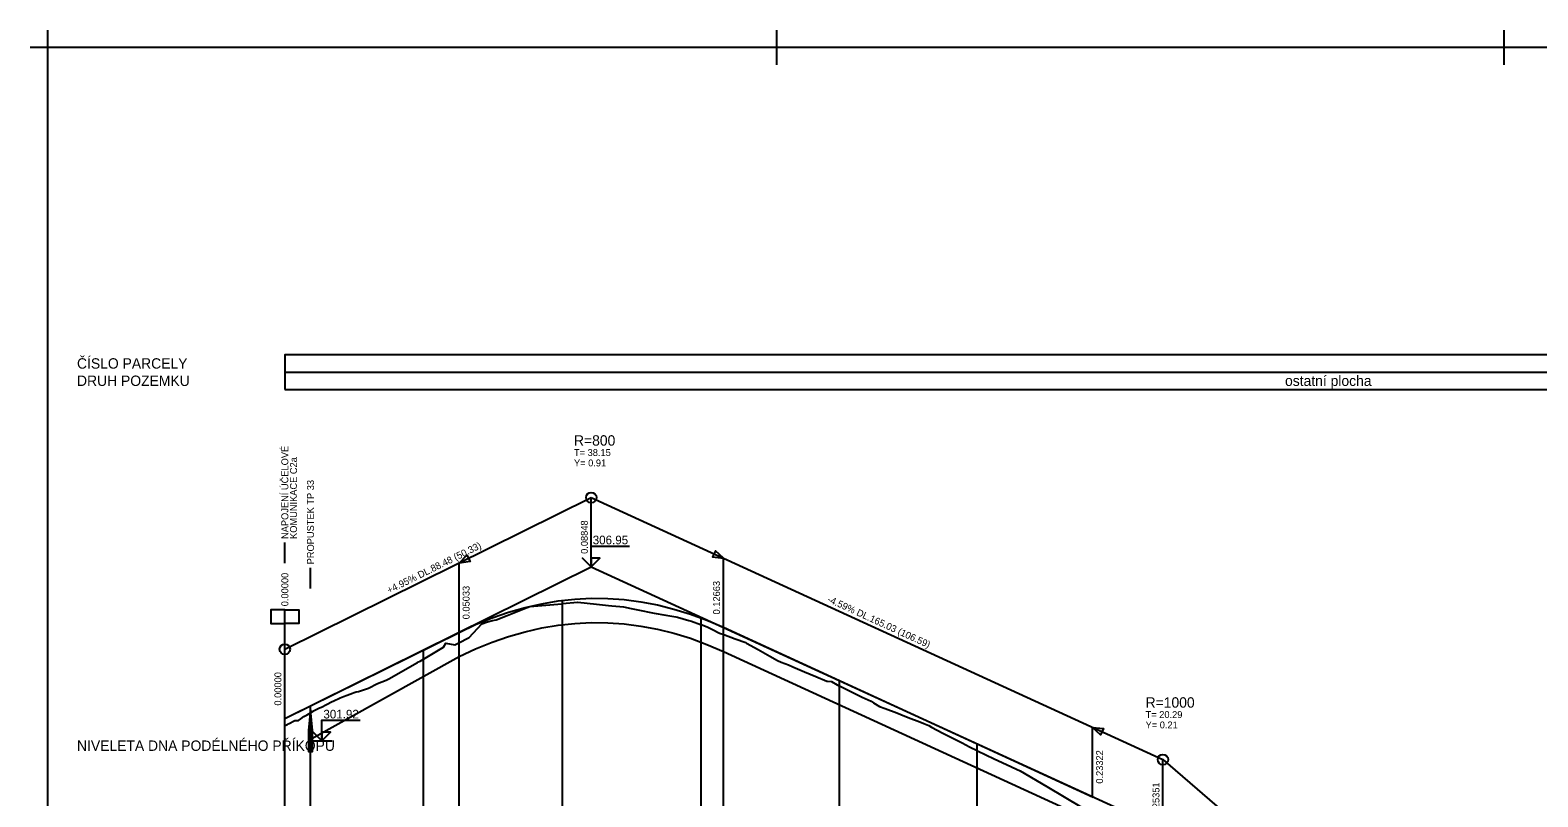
# Model space of a CAD drawing. Extents: x -4 to 847, y -64 to 540.
# Drawn here: x -3.5 to 431.8, y 318.1 to 539.5 of the extents above; entities that cross this region are included whole.
import ezdxf

# ---------------------------------------------------------------- set-up
doc = ezdxf.new("R2010")
doc.units = 0
for name, color, linetype in [('KOTA', 7, 'Continuous'), ('KRIZENI', 7, 'Continuous'), ('NOVY_STAV', 7, 'Continuous'), ('NS_OBLOUK', 7, 'Continuous'), ('POPISY_NAD_TERENEM', 7, 'Continuous'), ('PRIKOPY', 7, 'Continuous'), ('REZY_PO', 7, 'Continuous'), ('SESTAVY_REZU_PO', 7, 'Continuous'), ('SVK_STAT', 7, 'Continuous'), ('TABULKY', 7, 'Continuous'), ('ZNACKY', 7, 'Continuous')]:
    doc.layers.add(name, color=color, linetype=linetype)

msp = doc.modelspace()

# ---------------------------------------------------------------- linework, layer by layer
for p, q in [((1.47, 539.52), (1.47, 529.52)), ((1.47, 539.52), (1.47, 529.52)), ((1.47, 539.52), (1.47, 529.52)), ((1.47, 539.52), (1.47, 529.52)), ((1.47, 539.52), (1.47, 529.52)), ((1.47, 539.52), (1.47, 529.52)), ((1.47, 539.52), (1.47, 529.52)), ((1.47, 539.52), (1.47, 529.52)), ((1.47, 539.52), (1.47, 529.52)), ((1.47, 539.52), (1.47, 529.52)), ((1.47, 539.52), (1.47, 529.52)), ((1.47, 539.52), (1.47, 529.52)), ((1.47, 539.52), (1.47, 529.52)), ((1.47, 539.52), (1.47, 529.52)), ((1.47, 539.52), (1.47, 529.52)), ((1.47, 539.52), (1.47, 529.52)), ((1.47, 539.52), (1.47, 529.52)), ((1.47, 539.52), (1.47, 529.52)), ((1.47, 539.52), (1.47, 529.52)), ((1.47, 539.52), (1.47, 529.52)), ((1.47, 539.52), (1.47, 529.52)), ((1.47, 539.52), (1.47, 529.52)), ((1.47, 539.52), (1.47, 529.52)), ((1.47, 539.52), (1.47, 529.52)), ((1.47, 539.52), (1.47, 529.52)), ((1.47, 539.52), (1.47, 529.52)), ((1.47, 539.52), (1.47, 529.52)), ((1.47, 539.52), (1.47, 529.52)), ((1.47, 539.52), (1.47, 529.52)), ((1.47, 539.52), (1.47, 529.52)), ((1.47, 539.52), (1.47, 529.52)), ((1.47, 539.52), (1.47, 529.52)), ((1.47, 539.52), (1.47, 529.52)), ((1.47, 539.52), (1.47, 529.52)), ((1.47, 539.52), (1.47, 529.52)), ((1.47, 539.52), (1.47, 529.52)), ((1.47, 539.52), (1.47, 529.52)), ((1.47, 539.52), (1.47, 529.52)), ((1.47, 539.52), (1.47, 529.52)), ((1.47, 539.52), (1.47, 529.52)), ((1.47, 539.52), (1.47, 529.52)), ((1.47, 539.52), (1.47, 529.52)), ((1.47, 539.52), (1.47, 529.52)), ((1.47, 539.52), (1.47, 529.52)), ((1.47, 539.52), (1.47, 529.52)), ((1.47, 539.52), (1.47, 529.52)), ((1.47, 539.52), (1.47, 529.52)), ((1.47, 539.52), (1.47, 529.52)), ((1.47, 539.52), (1.47, 529.52)), ((1.47, 539.52), (1.47, 529.52)), ((1.47, 539.52), (1.47, 529.52)), ((1.47, 539.52), (1.47, 529.52)), ((1.47, 539.52), (1.47, 529.52)), ((1.47, 539.52), (1.47, 529.52)), ((1.47, 539.52), (1.47, 529.52)), ((1.47, 539.52), (1.47, 529.52)), ((1.47, 539.52), (1.47, 529.52)), ((1.47, 539.52), (1.47, 529.52)), ((1.47, 539.52), (1.47, 529.52)), ((1.47, 539.52), (1.47, 529.52)), ((211.97, 539.52), (211.97, 529.52)), ((211.97, 539.52), (211.97, 529.52)), ((211.97, 539.52), (211.97, 529.52)), ((211.97, 539.52), (211.97, 529.52)), ((211.97, 539.52), (211.97, 529.52)), ((211.97, 539.52), (211.97, 529.52)), ((211.97, 539.52), (211.97, 529.52)), ((211.97, 539.52), (211.97, 529.52)), ((211.97, 539.52), (211.97, 529.52)), ((211.97, 539.52), (211.97, 529.52)), ((211.97, 539.52), (211.97, 529.52)), ((211.97, 539.52), (211.97, 529.52)), ((211.97, 539.52), (211.97, 529.52)), ((211.97, 539.52), (211.97, 529.52)), ((211.97, 539.52), (211.97, 529.52)), ((211.97, 539.52), (211.97, 529.52)), ((211.97, 539.52), (211.97, 529.52)), ((211.97, 539.52), (211.97, 529.52)), ((211.97, 539.52), (211.97, 529.52)), ((211.97, 539.52), (211.97, 529.52)), ((211.97, 539.52), (211.97, 529.52)), ((211.97, 539.52), (211.97, 529.52)), ((211.97, 539.52), (211.97, 529.52)), ((211.97, 539.52), (211.97, 529.52)), ((211.97, 539.52), (211.97, 529.52)), ((211.97, 539.52), (211.97, 529.52)), ((211.97, 539.52), (211.97, 529.52)), ((211.97, 539.52), (211.97, 529.52)), ((211.97, 539.52), (211.97, 529.52)), ((211.97, 539.52), (211.97, 529.52)), ((421.97, 539.52), (421.97, 529.52)), ((421.97, 539.52), (421.97, 529.52)), ((421.97, 539.52), (421.97, 529.52)), ((421.97, 539.52), (421.97, 529.52)), ((421.97, 539.52), (421.97, 529.52)), ((421.97, 539.52), (421.97, 529.52)), ((421.97, 539.52), (421.97, 529.52)), ((421.97, 539.52), (421.97, 529.52)), ((421.97, 539.52), (421.97, 529.52)), ((421.97, 539.52), (421.97, 529.52)), ((421.97, 539.52), (421.97, 529.52)), ((421.97, 539.52), (421.97, 529.52)), ((421.97, 539.52), (421.97, 529.52)), ((421.97, 539.52), (421.97, 529.52)), ((421.97, 539.52), (421.97, 529.52)), ((421.97, 539.52), (421.97, 529.52)), ((421.97, 539.52), (421.97, 529.52)), ((421.97, 539.52), (421.97, 529.52)), ((421.97, 539.52), (421.97, 529.52)), ((421.97, 539.52), (421.97, 529.52)), ((6.47, 534.52), (-3.53, 534.52)), ((6.47, 534.52), (-3.53, 534.52)), ((6.47, 534.52), (-3.53, 534.52)), ((6.47, 534.52), (-3.53, 534.52)), ((6.47, 534.52), (-3.53, 534.52)), ((6.47, 534.52), (-3.53, 534.52)), ((6.47, 534.52), (-3.53, 534.52)), ((6.47, 534.52), (-3.53, 534.52)), ((6.47, 534.52), (-3.53, 534.52)), ((6.47, 534.52), (-3.53, 534.52)), ((6.47, 534.52), (-3.53, 534.52)), ((6.47, 534.52), (-3.53, 534.52)), ((6.47, 534.52), (-3.53, 534.52)), ((6.47, 534.52), (-3.53, 534.52)), ((6.47, 534.52), (-3.53, 534.52)), ((6.47, 534.52), (-3.53, 534.52)), ((6.47, 534.52), (-3.53, 534.52)), ((6.47, 534.52), (-3.53, 534.52)), ((6.47, 534.52), (-3.53, 534.52)), ((6.47, 534.52), (-3.53, 534.52)), ((6.47, 534.52), (-3.53, 534.52)), ((6.47, 534.52), (-3.53, 534.52)), ((6.47, 534.52), (-3.53, 534.52)), ((6.47, 534.52), (-3.53, 534.52)), ((6.47, 534.52), (-3.53, 534.52)), ((6.47, 534.52), (-3.53, 534.52)), ((6.47, 534.52), (-3.53, 534.52)), ((6.47, 534.52), (-3.53, 534.52)), ((6.47, 534.52), (-3.53, 534.52)), ((6.47, 534.52), (-3.53, 534.52)), ((6.47, 534.52), (-3.53, 534.52)), ((6.47, 534.52), (-3.53, 534.52)), ((6.47, 534.52), (-3.53, 534.52)), ((6.47, 534.52), (-3.53, 534.52)), ((6.47, 534.52), (-3.53, 534.52)), ((6.47, 534.52), (-3.53, 534.52)), ((6.47, 534.52), (-3.53, 534.52)), ((6.47, 534.52), (-3.53, 534.52)), ((6.47, 534.52), (-3.53, 534.52)), ((6.47, 534.52), (-3.53, 534.52)), ((6.47, 534.52), (-3.53, 534.52)), ((6.47, 534.52), (-3.53, 534.52)), ((6.47, 534.52), (-3.53, 534.52)), ((6.47, 534.52), (-3.53, 534.52)), ((6.47, 534.52), (-3.53, 534.52)), ((6.47, 534.52), (-3.53, 534.52)), ((6.47, 534.52), (-3.53, 534.52)), ((6.47, 534.52), (-3.53, 534.52)), ((6.47, 534.52), (-3.53, 534.52)), ((6.47, 534.52), (-3.53, 534.52)), ((6.47, 534.52), (-3.53, 534.52)), ((6.47, 534.52), (-3.53, 534.52)), ((6.47, 534.52), (-3.53, 534.52)), ((6.47, 534.52), (-3.53, 534.52)), ((6.47, 534.52), (-3.53, 534.52)), ((6.47, 534.52), (-3.53, 534.52)), ((6.47, 534.52), (-3.53, 534.52)), ((6.47, 534.52), (-3.53, 534.52)), ((6.47, 534.52), (-3.53, 534.52)), ((6.47, 534.52), (-3.53, 534.52)), ((216.97, 534.52), (206.97, 534.52)), ((216.97, 534.52), (206.97, 534.52)), ((216.97, 534.52), (206.97, 534.52)), ((216.97, 534.52), (206.97, 534.52)), ((216.97, 534.52), (206.97, 534.52)), ((216.97, 534.52), (206.97, 534.52)), ((216.97, 534.52), (206.97, 534.52)), ((216.97, 534.52), (206.97, 534.52)), ((216.97, 534.52), (206.97, 534.52)), ((216.97, 534.52), (206.97, 534.52)), ((216.97, 534.52), (206.97, 534.52)), ((216.97, 534.52), (206.97, 534.52)), ((216.97, 534.52), (206.97, 534.52)), ((216.97, 534.52), (206.97, 534.52)), ((216.97, 534.52), (206.97, 534.52)), ((216.97, 534.52), (206.97, 534.52)), ((216.97, 534.52), (206.97, 534.52)), ((216.97, 534.52), (206.97, 534.52)), ((216.97, 534.52), (206.97, 534.52)), ((216.97, 534.52), (206.97, 534.52)), ((216.97, 534.52), (206.97, 534.52)), ((216.97, 534.52), (206.97, 534.52)), ((216.97, 534.52), (206.97, 534.52)), ((216.97, 534.52), (206.97, 534.52)), ((216.97, 534.52), (206.97, 534.52)), ((216.97, 534.52), (206.97, 534.52)), ((216.97, 534.52), (206.97, 534.52)), ((216.97, 534.52), (206.97, 534.52)), ((216.97, 534.52), (206.97, 534.52)), ((216.97, 534.52), (206.97, 534.52)), ((426.97, 534.52), (416.97, 534.52)), ((426.97, 534.52), (416.97, 534.52)), ((426.97, 534.52), (416.97, 534.52)), ((426.97, 534.52), (416.97, 534.52)), ((426.97, 534.52), (416.97, 534.52)), ((426.97, 534.52), (416.97, 534.52)), ((426.97, 534.52), (416.97, 534.52)), ((426.97, 534.52), (416.97, 534.52)), ((426.97, 534.52), (416.97, 534.52)), ((426.97, 534.52), (416.97, 534.52)), ((426.97, 534.52), (416.97, 534.52)), ((426.97, 534.52), (416.97, 534.52)), ((426.97, 534.52), (416.97, 534.52)), ((426.97, 534.52), (416.97, 534.52)), ((426.97, 534.52), (416.97, 534.52)), ((426.97, 534.52), (416.97, 534.52)), ((426.97, 534.52), (416.97, 534.52)), ((426.97, 534.52), (416.97, 534.52)), ((426.97, 534.52), (416.97, 534.52)), ((426.97, 534.52), (416.97, 534.52))]:
    msp.add_line(p, q)
msp.add_lwpolyline([(841.97, 534.52), (1.47, 534.52), (1.47, -59.48), (841.97, -59.48)], close=True)
at = {"layer": 'KOTA'}
for points in [[(158.48, 384.52), (155.98, 387.02), (158.48, 384.52), (158.48, 390.52), (169.48, 390.52)], [(158.48, 384.52), (160.98, 387.02), (158.48, 387.02), (158.48, 384.52)], [(158.48, 384.52), (160.98, 387.02), (158.48, 387.02)], [(158.48, 384.52), (158.48, 384.52)], [(80.71, 334.23), (78.21, 336.73), (80.71, 334.23), (80.71, 340.23), (91.71, 340.23)], [(80.71, 334.23), (78.21, 336.73), (80.71, 334.23), (80.71, 340.23), (91.71, 340.23)], [(80.71, 334.23), (83.21, 336.73), (80.71, 336.73), (80.71, 334.23)], [(80.71, 334.23), (83.21, 336.73), (80.71, 336.73)], [(80.71, 334.23), (83.21, 336.73), (80.71, 336.73), (80.71, 334.23)], [(80.71, 334.23), (83.21, 336.73), (80.71, 336.73)], [(77.41, 334.23), (80.71, 334.23), (83.71, 334.23)], [(77.41, 334.23), (80.71, 334.23), (83.71, 334.23)]]:
    msp.add_lwpolyline(points, dxfattribs=at)
at = {"layer": 'KRIZENI'}
for points in [[(78.01, 337.23), (77.41, 343.23), (76.81, 337.23), (77.41, 331.23)], [(77.71, 337.23), (77.41, 340.23), (77.11, 337.23), (77.41, 334.23)]]:
    msp.add_lwpolyline(points, close=True, dxfattribs=at)
msp.add_lwpolyline([(76.81, 337.23), (76.81, 331.23), (78.01, 331.23), (78.01, 337.23)], dxfattribs=at)
at = {"layer": 'NOVY_STAV'}
for points in [[(70, 360.7), (158.48, 404.52)], [(158.48, 384.52), (158.48, 404.52)], [(158.48, 404.52), (323.51, 328.85)], [(70, 340.7), (158.48, 384.52), (323.51, 308.85), (437.61, 210.22), (552.15, 190.26), (662.38, 149.89)], [(70, 340.7), (120.29, 365.6), (125.06, 367.83), (129.84, 369.77), (134.61, 371.42), (139.38, 372.79), (144.16, 373.88), (148.93, 374.68), (153.7, 375.2), (158.48, 375.43), (163.25, 375.38), (168.01, 375.05), (172.78, 374.43), (177.55, 373.53), (182.32, 372.34), (187.09, 370.88), (191.86, 369.12), (196.63, 367.08), (303.42, 318.02)], [(70, 340.7), (70, 360.7)], [(323.51, 308.85), (323.51, 328.85)], [(323.51, 328.85), (437.61, 230.22)]]:
    msp.add_lwpolyline(points, dxfattribs=at)
for centre in [(158.48, 404.52), (70, 360.7), (323.51, 328.85)]:
    msp.add_circle(centre, 1.5, dxfattribs=at)
at = {"layer": 'NS_OBLOUK'}
for points in [[(120.33, 385.62), (122.57, 387.85), (123.46, 386.06), (120.33, 385.62)], [(196.63, 387.03), (194.32, 389.18), (193.48, 387.37), (196.63, 387.03)], [(120.33, 365.62), (120.33, 385.62)], [(196.63, 367.03), (196.63, 387.03)], [(303.22, 318.15), (303.22, 338.15)], [(303.22, 338.15), (306.36, 337.81), (305.53, 335.99), (303.22, 338.15)]]:
    msp.add_lwpolyline(points, dxfattribs=at)
for points in [[(120.33, 385.62), (122.57, 387.85), (123.46, 386.06)], [(196.63, 387.03), (194.32, 389.18), (193.48, 387.37)], [(303.22, 338.15), (306.36, 337.81), (305.53, 335.99)]]:
    msp.add_lwpolyline(points, close=True, dxfattribs=at)
at = {"layer": 'POPISY_NAD_TERENEM'}
for points in [[(70, 385.57), (70, 391.57)], [(77.41, 378.24), (77.41, 384.24)]]:
    msp.add_lwpolyline(points, dxfattribs=at)
at = {"layer": 'PRIKOPY'}
msp.add_lwpolyline([(76.89, 334.48), (120.29, 358.6), (125.06, 360.83), (129.84, 362.77), (134.61, 364.42), (139.38, 365.79), (144.16, 366.88), (148.93, 367.68), (153.7, 368.2), (158.48, 368.43), (163.25, 368.38), (168.01, 368.05), (172.78, 367.43), (177.55, 366.53), (182.32, 365.34), (187.09, 363.88), (191.86, 362.12), (196.63, 360.08), (303.42, 311.02)], dxfattribs=at)
at = {"layer": 'REZY_PO'}
msp.add_lwpolyline([(70, 338.7), (70.74, 339), (71.04, 339.16), (72.84, 340.12), (72.94, 340.18), (73.94, 340.16), (74.63, 340.65), (75.52, 341.28), (76.42, 341.81), (78.21, 342.85), (78.3, 342.9), (80, 343.76), (80.55, 344.03), (82, 344.78), (83.71, 345.64), (84, 345.77), (86, 346.66), (86.91, 347.05), (88, 347.47), (89.53, 348.03), (90, 348.18), (90.62, 348.38), (91.23, 348.56), (94.2, 349.46), (96.79, 350.84), (99.29, 351.82), (100, 352.22), (108.28, 356.91), (108.56, 357.11), (109.1, 357.31), (110, 357.85), (110.06, 357.89), (115.78, 361.3), (116.49, 362.48), (119.06, 362.03), (120, 362.49), (123.26, 364.1), (126.86, 368.07), (128.47, 368.61), (130, 368.99), (130.97, 369.23), (134.21, 370.49), (137.52, 371.78), (140, 372.74), (140.76, 373.03), (150, 373.88), (150.12, 373.9), (154.47, 374.3), (154.52, 374.3), (154.54, 374.3), (154.56, 374.3), (154.59, 374.3), (160, 373.72), (163.49, 373.36), (164.4, 373.26), (166.75, 373.07), (167.74, 372.99), (170, 372.48), (173.33, 371.77), (175.19, 371.39), (176.67, 371.12), (180, 370.55), (182.84, 370.08), (183.33, 369.94), (186.67, 369.03), (187.37, 368.84), (190, 367.9), (190.08, 367.87), (190.16, 367.84), (191.9, 367.22), (193.44, 366.44), (195.53, 365.37), (196.72, 364.95), (200, 363.76), (203.07, 362.64), (203.33, 362.49), (206.67, 360.61), (210, 358.72), (212.24, 357.45), (213.33, 357), (215.44, 356.17), (216.67, 355.64), (220, 354.22), (223.33, 352.82), (226.46, 351.53), (226.67, 351.51), (227.84, 351.4), (229.43, 350.48), (230, 350.19), (230.07, 350.16), (230.13, 350.12), (233.42, 348.49), (236.71, 346.89), (239.27, 345.68), (240, 345.23), (241.7, 344.21), (243.33, 343.58), (246.67, 342.31), (247.87, 341.85), (250, 341.02), (253.33, 339.73), (254.48, 339.29), (255.91, 338.65), (256.67, 338.26), (260, 336.52), (263.29, 334.81), (265.53, 333.66), (266.58, 333.1), (267.66, 332.54), (267.81, 332.47), (267.82, 332.46), (269.87, 331.45), (269.94, 331.42), (270, 331.39), (274.8, 329.09), (279.61, 326.87), (280, 326.69), (282.26, 325.65), (290, 321.07), (300, 315.14)], dxfattribs=at)
at = {"layer": 'SVK_STAT'}
for points in [[(150.12, 98), (150.12, 374.81)], [(190.16, 98), (190.16, 369.75)], [(196.63, 98), (196.63, 367.08)], [(120.29, 98), (120.29, 365.6)], [(110.06, 98), (110.06, 360.54)], [(230.13, 98), (230.13, 351.69)], [(77.41, 98), (77.41, 344.37)], [(70, 98), (70, 340.7)], [(269.87, 98), (269.87, 333.44)]]:
    msp.add_lwpolyline(points, dxfattribs=at)
at = {"layer": 'TABULKY'}
for points in [[(70, 435.76), (662.38, 435.76), (662.38, 445.76), (70, 445.76), (70, 435.76)], [(70, 440.76), (662.38, 440.76)]]:
    msp.add_lwpolyline(points, dxfattribs=at)
at = {"layer": 'ZNACKY'}
for points in [[(70, 340.7), (70, 372.13), (66, 372.13), (66, 368.13), (70, 368.13)], [(70, 372.13), (74, 372.13), (74, 368.13), (70, 368.13)]]:
    msp.add_lwpolyline(points, dxfattribs=at)

# ---------------------------------------------------------------- texts
at = {"layer": 'KOTA'}
for s, p in [('306.95', (158.89, 391.02)), ('301.92', (81.13, 340.73)), ('301.92', (81.13, 340.73))]:
    msp.add_text(s, height=2.5, dxfattribs=at).set_placement(p)
at = {"layer": 'NOVY_STAV'}
for s, rotation, p in [(' 0.08848', 90, (157.48, 387.52)), ('+4.95% DL.88.48 (50.33)', 26.3468, (100.1, 376.72)), ('-4.59% DL.165.03 (106.59)', 335.368, (226.46, 374.45)), (' 0.00000', 90, (69, 343.7)), (' 0.25351', 90, (322.51, 311.85))]:
    msp.add_text(s, height=2, rotation=rotation, dxfattribs=at).set_placement(p)
at = {"layer": 'NS_OBLOUK'}
for s, height, p in [('R=800', 3, (153.48, 419.52)), ('T= 38.15', 2, (153.48, 416.52)), ('Y= 0.91', 2, (153.48, 413.52)), ('R=1000', 3, (318.51, 343.85)), ('T= 20.29', 2, (318.51, 340.85)), ('Y= 0.21', 2, (318.51, 337.85))]:
    msp.add_text(s, height=height, dxfattribs=at).set_placement(p)
for s, p in [(' 0.05033', (123.33, 368.62)), (' 0.12663', (195.63, 370.03)), (' 0.23322', (306.22, 321.15))]:
    msp.add_text(s, height=2, rotation=90, dxfattribs=at).set_placement(p)
at = {"layer": 'POPISY_NAD_TERENEM'}
for s, p in [('NAPOJENÍ ÚČELOVÉ', (71, 392.57)), ('KOMUNIKACE C2a', (73.5, 392.57)), ('PROPUSTEK TP 33', (78.41, 385.24))]:
    msp.add_text(s, height=2, rotation=90, dxfattribs=at).set_placement(p)
at = {"layer": 'SESTAVY_REZU_PO'}
msp.add_text('NIVELETA DNA PODÉLNÉHO PŘÍKOPU', height=3, dxfattribs=at).set_placement((10, 331.37))
at = {"layer": 'TABULKY'}
for s, p in [('ČÍSLO PARCELY', (10, 441.76)), ('DRUH POZEMKU', (10, 436.76)), ('ostatní plocha', (358.77, 436.76))]:
    msp.add_text(s, height=3, dxfattribs=at).set_placement(p)
at = {"layer": 'ZNACKY'}
msp.add_text('0.00000', height=2, rotation=90, dxfattribs=at).set_placement((71, 373.13))

doc.saveas('drawing.dxf')
